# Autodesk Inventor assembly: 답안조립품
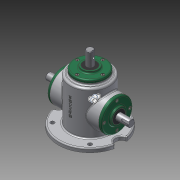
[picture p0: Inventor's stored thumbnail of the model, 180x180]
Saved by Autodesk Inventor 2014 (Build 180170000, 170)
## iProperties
Created: 2018-04
Part Number: 답안조립품
Document SubType Name: Assembly
Designer: OA62
Author: OA62
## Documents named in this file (16)
- C:\Users\OA62\Desktop\480408V1004\답안조립품.iam
- C:\Users\OA62\Desktop\480408V1004\본체.ipt
- C:\Users\OA62\Desktop\480408V1004\커버.ipt
- C:\Users\OA62\Desktop\480408V1004\베어링 6203.ipt
- C:\Users\OA62\Desktop\480408V1004\오일 실.ipt
- 오일 실.ipt
- C:\Users\OA62\Desktop\480408V1004\메인 축.ipt
- 메인 축.ipt
- C:\Users\OA62\Desktop\480408V1004\키 5x5.ipt
- C:\Users\OA62\Desktop\480408V1004\메인 베벨기어.ipt
- C:\Users\OA62\Desktop\480408V1004\서브 축.ipt
- 서브 축.ipt
- C:\Users\OA62\Desktop\480408V1004\키 4x4.ipt
- C:\Users\OA62\Desktop\480408V1004\서브 베벨기어.ipt
- C:\Users\OA62\Desktop\480408V1004\볼트 M4.ipt
- 볼트 M4.ipt
